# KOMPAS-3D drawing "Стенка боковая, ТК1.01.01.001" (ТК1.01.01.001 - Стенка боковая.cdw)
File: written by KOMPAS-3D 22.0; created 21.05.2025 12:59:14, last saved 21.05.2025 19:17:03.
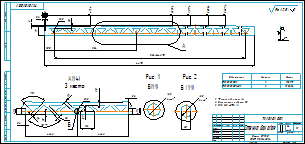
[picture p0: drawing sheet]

Sheet 1: A4x3, landscape

Document properties: Автор: user; Знак неуказанной шероховатости: 4; Параметр неуказанной шероховатости: Ra 12,5; Масса: 11.51708; Форматы листов документа: A4@4~3; Полное имя файла: ..\Стенка боковая.m3d

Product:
- Part/product: Стенка боковая  | designation ТК1.01.01.001
    Масса: 11.51708
    Форматы листов документа: A4@4~3
- Part/product: Стенка боковая  | designation ТК1.01.01.001-01
    Масса: 11.528421

Title block, sheet 1: Наименование: Стенка боковая; designation: ТК1.01.01.001; Материал: Сталь 09Г2С / ГОСТ 19281-2014; Масса: 11,52; Количество листов документа: 1; Форматы листов документа: A4 3; stored path: D:\Рабочая папка\АРХИВ\612\05\Задание №6 - Тележка для крыши\3Д\Тележка в сборе\Корпус тележки\КД\Стенка боковая.cdw

Views: Проекционный вид 2, Выносной элемент 3, Проекционный вид 4, Выносной элемент 5, Вид 6, Выносной элемент А, Выносной элемент, Выносной элемент Б
Referenced files in D:\Работа\2025\5. Май\Задание №6 - Тележка для крыши\3Д\Тележка в сборе\Корпус тележки\: Стенка боковая.m3d
Referenced files in D:\Рабочая папка\АРХИВ\612\05\Задание №6 - Тележка для крыши\3Д\Тележка в сборе\Корпус тележки\: Стенка боковая.m3d
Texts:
  ТК1.01.01.001-01
  Рисунок
  ТК1.01.01.001 - 01
  Стиль таблицы исполнений
  Рис. 1
  Рис. 2
  Ra 12,5
  Ra 12,5 ( )
  BOSimple***Material:4ccf0190-16b6-4223-9222-aa108d28a442
  ТК1.01.01.001 Стенка боковая
Dimensions and other numbers on the sheet: 4470; 5,6; 100; 854; 854x5=; 4270; 471,4; 1325,4; 2179,4; 3033,4; 3887,4; 97; 8; 25; 20; 1; 11,5171; 2; 11,5284; 0; 3 места; 49,1; 57; 114; 424,2; 5; 6 отв.; 1:1; 11,52

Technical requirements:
  *Размеры для справок.
  Неуказанные радиусы R5.
  H12, h12, ±IT12/2.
